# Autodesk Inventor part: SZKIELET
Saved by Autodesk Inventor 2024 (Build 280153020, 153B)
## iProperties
_SkeletonDoc: Frame Skeleton File
_Version: 15.0.0
Company: ATC
Created: 2023-03
Part Number: SZKIELET
Document SubType Name: Modeling
Designer: Andrzej Jaskulski
Density: 1 g/cm^3
Material: Ogólny
Appearance: Domyślna
Checked By: A.J.
Engr Approved By: Andrzej Jaskulski
Mfg Approved By: Andrzej Jaskulski
Authority: A.J.
Author: Andrzej Jaskulski
Revision Number: 1/24
Title: A.J.: Kurs R2024-MEP
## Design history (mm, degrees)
sketch "Szkielet odniesienia"
